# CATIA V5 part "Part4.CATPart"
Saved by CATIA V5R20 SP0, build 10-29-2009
Part number: Part4
Bounding box of the stored display mesh (mm): x 20 to 50, y 19.6 to 60, z 12 to 50
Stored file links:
  C:\Users\Ehsan Fathi\Desktop\Part4.CATPart
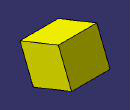
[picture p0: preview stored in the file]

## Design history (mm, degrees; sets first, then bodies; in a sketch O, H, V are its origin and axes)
Body1 (main body)
  DatumSurface1
  DatumCurve1
  Sketch1 on face of DatumSurface1, origin (50, 0, 0), H (0, 1, 0), V (0, 0, 1)
    line L1 (30, 12) -> (60, 24)
    line L2 (60, 24) -> (49.6, 50)
    line L3 (49.6, 50) -> (19.6, 38)
    line L4 (19.6, 38) -> (30, 12)
    parallelism: L4 L2, L1 L3
    perpendicularity: L1 L2
  Pad1: profile Sketch1, direction (-1, 0, 0), length 30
